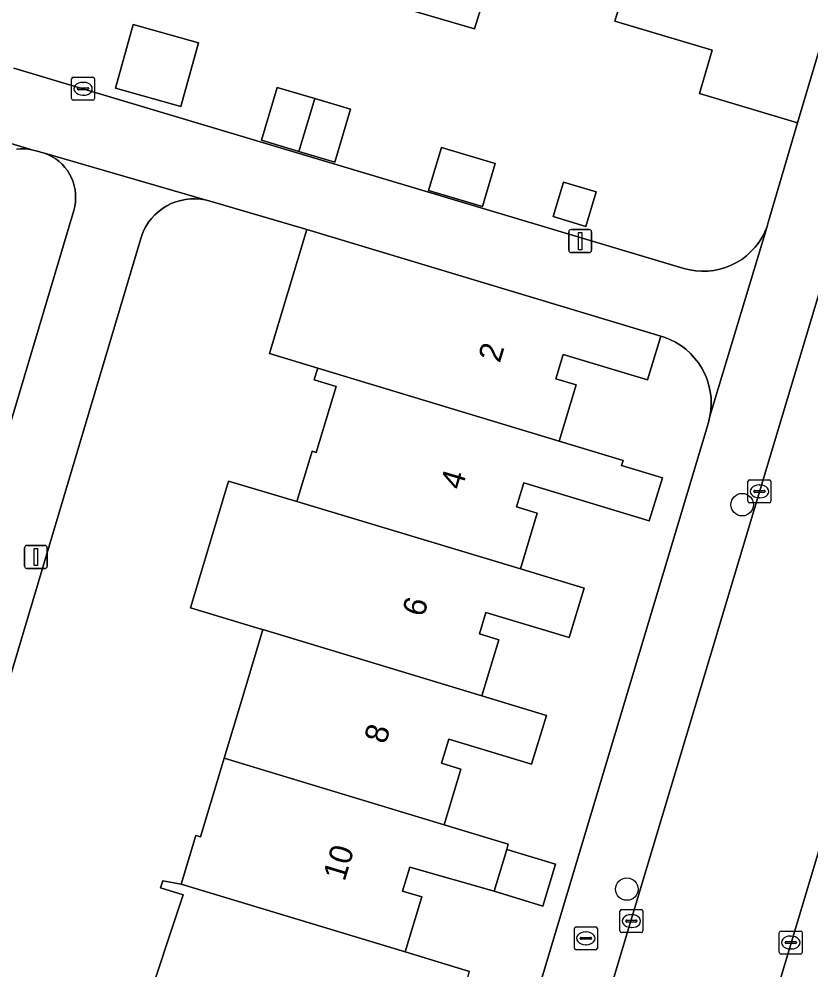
# Model space of a CAD drawing. Extents: x 162184 to 163154, y 385507 to 386516.
# Drawn here: x 162667.22 to 162701.67, y 386139.27 to 386180.64 of the extents above; entities that cross this region are included whole.
import ezdxf

# ---------------------------------------------------------------- set-up
doc = ezdxf.new("R2010")
doc.units = 0
for name, color, linetype in [('IMGEO_Boom', 7, 'Continuous'), ('IMGEO_Brandkraan', 7, 'Continuous'), ('IMGEO_Erf', 7, 'Continuous'), ('IMGEO_Groenvoorziening', 7, 'Continuous'), ('IMGEO_Kolk', 7, 'Continuous'), ('IMGEO_Lichtmast', 7, 'Continuous'), ('IMGEO_Pand', 7, 'Continuous'), ('IMGEO_Pand_nummerreeks', 7, 'Continuous'), ('IMGEO_Rijbaan_lokaal_open', 7, 'Continuous'), ('IMGEO_Voetpad_open', 7, 'Continuous')]:
    doc.layers.add(name, color=color, linetype=linetype)

msp = doc.modelspace()

# ---------------------------------------------------------------- linework, layer by layer
at = {"layer": 'IMGEO_Boom'}
for centre in [(162698.674, 386159.513), (162693.661, 386142.787)]:
    msp.add_circle(centre, 0.489, dxfattribs=at)
at = {"layer": 'IMGEO_Brandkraan'}
for p, q in [((162691.375, 386140.218), (162691.375, 386141.07)), ((162691.45, 386141.144), (162692.302, 386141.144)), ((162692.376, 386141.07), (162692.376, 386140.218)), ((162691.634, 386140.638), (162691.634, 386140.65)), ((162691.677, 386140.687), (162692.075, 386140.687)), ((162691.863, 386140.924), (162691.888, 386140.924)), ((162692.118, 386140.65), (162692.118, 386140.638)), ((162692.072, 386140.601), (162691.674, 386140.601)), ((162691.886, 386140.364), (162691.861, 386140.364)), ((162692.302, 386140.144), (162691.45, 386140.144))]:
    msp.add_line(p, q, dxfattribs=at)
for points in [[(162691.375, 386140.218), (162691.375, 386141.07)], [(162691.45, 386141.144), (162692.302, 386141.144)], [(162692.376, 386141.07), (162692.376, 386140.218)], [(162692.302, 386140.144), (162691.45, 386140.144)]]:
    msp.add_lwpolyline(points, dxfattribs=at)
for centre, radius, start, end in [((162691.452, 386141.068), 0.0765, 91.552, 178.448), ((162691.452, 386141.068), 0.0765, 91.552, 178.448), ((162692.3, 386141.068), 0.0765, 1.552, 88.448), ((162692.3, 386141.068), 0.0765, 1.552, 88.448), ((162691.674, 386140.647), 0.0403, 85.8775, 175.7526), ((162691.671, 386140.637), 0.0366, 178.938, 274.7102), ((162692.075, 386140.644), 0.043, 264.8664, 352.4533), ((162692.079, 386140.649), 0.0386, 1.7309, 96.639), ((162691.452, 386140.22), 0.0765, 181.552, 268.448), ((162691.452, 386140.22), 0.0765, 181.552, 268.448), ((162692.3, 386140.22), 0.0765, 271.552, 358.448), ((162692.3, 386140.22), 0.0765, 271.552, 358.448)]:
    msp.add_arc(centre, radius, start, end, dxfattribs=at)
for centre, major_axis, ratio, start_param, end_param in [((162691.862, 386140.644), (-0.387, 0.002), 0.722429, 4.712389, 7.853982), ((162691.887, 386140.644), (-0.39, 0.002), 0.717154, 1.570796, 4.712389)]:
    msp.add_ellipse(centre, major_axis=major_axis, ratio=ratio, start_param=start_param, end_param=end_param, dxfattribs=at)
at = {"layer": 'IMGEO_Erf'}
for points in [[(162687.686, 386182.336), (162687.034, 386180.211), (162681.466, 386181.862)], [(162666.99, 386178.501), (162696.144, 386169.794), (162696.399, 386169.73), (162696.658, 386169.689), (162696.92, 386169.671), (162697.183, 386169.677), (162697.444, 386169.706), (162697.701, 386169.758), (162697.953, 386169.833), (162698.197, 386169.931), (162698.431, 386170.049), (162698.654, 386170.188), (162698.864, 386170.347), (162699.058, 386170.524), (162699.236, 386170.717), (162699.396, 386170.925), (162699.537, 386171.147), (162699.657, 386171.381), (162699.756, 386171.624), (162699.811, 386171.795), (162701.088, 386176.13), (162696.812, 386177.398), (162697.373, 386179.289), (162693.133, 386180.547), (162693.464, 386181.665)], [(162672.648, 386137.382), (162674.361, 386142.543), (162673.38, 386142.839), (162673.471, 386143.139), (162674.27, 386142.997), (162674.91, 386145.116), (162675.113, 386145.055), (162676.018, 386148.053), (162676.147, 386148.481), (162676.849, 386150.83), (162677.083, 386151.605), (162677.829, 386154.075), (162677.646, 386154.13), (162674.678, 386155.026), (162676.339, 386160.538), (162679.31, 386159.652), (162679.97, 386161.838), (162680.144, 386161.785), (162681.011, 386164.658), (162680.056, 386164.946), (162680.142, 386165.23), (162680.211, 386165.459), (162678.11, 386166.096), (162679.739, 386171.493), (162675.532, 386172.716), (162675.323, 386172.77), (162675.11, 386172.804), (162674.895, 386172.82), (162674.679, 386172.816), (162674.464, 386172.793), (162674.252, 386172.751), (162674.045, 386172.691), (162673.844, 386172.612), (162673.651, 386172.515), (162673.468, 386172.401), (162673.295, 386172.272), (162673.134, 386172.128), (162672.987, 386171.969), (162672.855, 386171.799), (162672.739, 386171.617), (162672.639, 386171.426), (162672.557, 386171.226), (162672.514, 386171.096), (162664.259, 386143.414)], [(162682.002, 386112.374), (162697.211, 386163.095), (162697.274, 386163.359), (162697.313, 386163.627), (162697.329, 386163.897), (162697.32, 386164.168), (162697.286, 386164.437), (162697.229, 386164.702), (162697.149, 386164.961), (162697.045, 386165.212), (162696.92, 386165.452), (162696.774, 386165.68), (162696.608, 386165.894), (162696.423, 386166.093), (162696.222, 386166.274), (162696.005, 386166.437), (162695.774, 386166.579), (162695.532, 386166.701), (162695.279, 386166.8), (162695.132, 386166.846), (162694.556, 386164.939), (162690.882, 386166.049), (162690.564, 386164.995), (162691.448, 386164.729), (162690.709, 386162.279), (162693.498, 386161.437), (162693.433, 386161.221), (162695.203, 386160.686), (162694.635, 386158.808), (162692.865, 386159.342), (162689.171, 386160.457), (162688.856, 386159.412), (162689.762, 386159.138), (162689.033, 386156.722), (162691.807, 386155.884), (162691.156, 386153.728), (162687.527, 386154.823), (162687.245, 386153.889), (162688.087, 386153.635), (162687.35, 386151.194), (162690.162, 386150.346), (162689.514, 386148.228), (162685.909, 386149.316), (162685.592, 386148.265), (162686.442, 386148.008), (162685.712, 386145.589), (162688.503, 386144.747), (162688.433, 386144.514), (162690.56, 386143.872), (162690.01, 386142.049), (162687.883, 386142.691), (162684.213, 386143.742), (162683.898, 386142.699), (162684.738, 386142.445), (162684.015, 386140.05), (162686.809, 386139.206)]]:
    msp.add_lwpolyline(points, dxfattribs=at)
for points in [[(162674.253, 386176.841), (162671.416, 386177.634), (162672.191, 386180.407), (162675.028, 386179.613)], [(162680.081, 386177.186), (162681.643, 386176.723), (162680.96, 386174.42), (162679.398, 386174.883), (162677.763, 386175.368), (162678.446, 386177.671)], [(162685.036, 386173.183), (162685.591, 386175.054), (162687.933, 386174.358), (162687.377, 386172.488)], [(162690.454, 386172.046), (162690.898, 386173.542), (162692.322, 386173.12), (162691.878, 386171.623)]]:
    msp.add_lwpolyline(points, close=True, dxfattribs=at)
at = {"layer": 'IMGEO_Groenvoorziening'}
msp.add_lwpolyline([(162661.394, 386144.815), (162669.599, 386172.319), (162669.643, 386172.494), (162669.671, 386172.673), (162669.683, 386172.854), (162669.679, 386173.035), (162669.658, 386173.214), (162669.622, 386173.391), (162669.57, 386173.565), (162669.503, 386173.733), (162669.421, 386173.894), (162669.324, 386174.047), (162669.215, 386174.191), (162669.093, 386174.325), (162668.96, 386174.447), (162668.816, 386174.557), (162668.663, 386174.654), (162668.502, 386174.736), (162668.335, 386174.804), (162668.162, 386174.857), (162668.132, 386174.864), (162667.782, 386174.948), (162667.618, 386174.98), (162667.452, 386174.997), (162667.285, 386174.999), (162667.118, 386174.986)], dxfattribs=at)
at = {"layer": 'IMGEO_Kolk'}
for p, q in [((162669.507, 386177.183), (162669.507, 386178.035)), ((162669.582, 386178.109), (162670.434, 386178.109)), ((162669.995, 386177.889), (162670.02, 386177.889)), ((162670.508, 386178.035), (162670.508, 386177.183)), ((162669.766, 386177.603), (162669.766, 386177.615)), ((162670.204, 386177.566), (162669.806, 386177.566)), ((162669.809, 386177.652), (162670.207, 386177.652)), ((162670.25, 386177.615), (162670.25, 386177.603)), ((162670.434, 386177.109), (162669.582, 386177.109)), ((162670.018, 386177.329), (162669.993, 386177.329)), ((162698.925, 386159.664), (162698.925, 386160.516)), ((162699, 386160.59), (162699.852, 386160.59)), ((162699.926, 386160.516), (162699.926, 386159.664)), ((162699.184, 386160.084), (162699.184, 386160.096)), ((162699.227, 386160.133), (162699.625, 386160.133)), ((162699.413, 386160.37), (162699.438, 386160.37)), ((162699.668, 386160.096), (162699.668, 386160.084)), ((162699.622, 386160.047), (162699.224, 386160.047)), ((162699.436, 386159.81), (162699.411, 386159.81)), ((162699.852, 386159.59), (162699, 386159.59)), ((162693.43, 386141.894), (162694.282, 386141.894)), ((162693.355, 386140.968), (162693.355, 386141.82)), ((162693.843, 386141.674), (162693.868, 386141.674)), ((162694.356, 386141.82), (162694.356, 386140.968)), ((162693.614, 386141.388), (162693.614, 386141.4)), ((162694.052, 386141.351), (162693.654, 386141.351)), ((162693.657, 386141.437), (162694.055, 386141.437)), ((162693.866, 386141.114), (162693.841, 386141.114)), ((162694.098, 386141.4), (162694.098, 386141.388)), ((162694.282, 386140.894), (162693.43, 386140.894)), ((162700.29, 386140.035), (162700.29, 386140.887)), ((162700.365, 386140.961), (162701.217, 386140.961)), ((162700.778, 386140.741), (162700.803, 386140.741)), ((162701.291, 386140.887), (162701.291, 386140.035)), ((162700.549, 386140.455), (162700.549, 386140.467)), ((162700.987, 386140.418), (162700.589, 386140.418)), ((162700.592, 386140.504), (162700.99, 386140.504)), ((162701.033, 386140.467), (162701.033, 386140.455)), ((162701.217, 386139.961), (162700.365, 386139.961)), ((162700.801, 386140.181), (162700.776, 386140.181))]:
    msp.add_line(p, q, dxfattribs=at)
for points in [[(162669.507, 386177.183), (162669.507, 386178.035)], [(162669.582, 386178.109), (162670.434, 386178.109)], [(162670.508, 386178.035), (162670.508, 386177.183)], [(162670.434, 386177.109), (162669.582, 386177.109)], [(162698.925, 386159.664), (162698.925, 386160.516)], [(162699, 386160.59), (162699.852, 386160.59)], [(162699.926, 386160.516), (162699.926, 386159.664)], [(162699.852, 386159.59), (162699, 386159.59)], [(162693.43, 386141.894), (162694.282, 386141.894)], [(162693.355, 386140.968), (162693.355, 386141.82)], [(162694.356, 386141.82), (162694.356, 386140.968)], [(162694.282, 386140.894), (162693.43, 386140.894)], [(162700.29, 386140.035), (162700.29, 386140.887)], [(162700.365, 386140.961), (162701.217, 386140.961)], [(162701.291, 386140.887), (162701.291, 386140.035)], [(162701.217, 386139.961), (162700.365, 386139.961)]]:
    msp.add_lwpolyline(points, dxfattribs=at)
for centre, radius, start, end in [((162669.584, 386178.033), 0.0765, 91.552, 178.448), ((162669.584, 386178.033), 0.0765, 91.552, 178.448), ((162670.432, 386178.033), 0.0765, 1.552, 88.448), ((162670.432, 386178.033), 0.0765, 1.552, 88.448), ((162669.806, 386177.612), 0.0403, 85.8775, 175.7526), ((162669.803, 386177.602), 0.0366, 178.938, 274.7102), ((162670.207, 386177.609), 0.043, 264.8664, 352.4533), ((162670.211, 386177.614), 0.0386, 1.7309, 96.639), ((162669.584, 386177.185), 0.0765, 181.552, 268.448), ((162669.584, 386177.185), 0.0765, 181.552, 268.448), ((162670.432, 386177.185), 0.0765, 271.552, 358.448), ((162670.432, 386177.185), 0.0765, 271.552, 358.448), ((162699.002, 386160.514), 0.0765, 91.552, 178.448), ((162699.002, 386160.514), 0.0765, 91.552, 178.448), ((162699.85, 386160.514), 0.0765, 1.552, 88.448), ((162699.85, 386160.514), 0.0765, 1.552, 88.448), ((162699.224, 386160.093), 0.0403, 85.8775, 175.7526), ((162699.221, 386160.083), 0.0366, 178.938, 274.7102), ((162699.625, 386160.09), 0.043, 264.8664, 352.4533), ((162699.629, 386160.095), 0.0386, 1.7309, 96.639), ((162699.002, 386159.666), 0.0765, 181.552, 268.448), ((162699.002, 386159.666), 0.0765, 181.552, 268.448), ((162699.85, 386159.666), 0.0765, 271.552, 358.448), ((162699.85, 386159.666), 0.0765, 271.552, 358.448), ((162693.432, 386141.818), 0.0765, 91.552, 178.448), ((162693.432, 386141.818), 0.0765, 91.552, 178.448), ((162694.28, 386141.818), 0.0765, 1.552, 88.448), ((162694.28, 386141.818), 0.0765, 1.552, 88.448), ((162693.654, 386141.397), 0.0403, 85.8775, 175.7526), ((162693.651, 386141.387), 0.0366, 178.938, 274.7102), ((162694.055, 386141.394), 0.043, 264.8664, 352.4533), ((162694.059, 386141.399), 0.0386, 1.7309, 96.639), ((162693.432, 386140.97), 0.0765, 181.552, 268.448), ((162693.432, 386140.97), 0.0765, 181.552, 268.448), ((162694.28, 386140.97), 0.0765, 271.552, 358.448), ((162694.28, 386140.97), 0.0765, 271.552, 358.448), ((162700.367, 386140.885), 0.0765, 91.552, 178.448), ((162700.367, 386140.885), 0.0765, 91.552, 178.448), ((162701.215, 386140.885), 0.0765, 1.552, 88.448), ((162701.215, 386140.885), 0.0765, 1.552, 88.448), ((162700.589, 386140.464), 0.0403, 85.8775, 175.7526), ((162700.586, 386140.454), 0.0366, 178.938, 274.7102), ((162700.99, 386140.461), 0.043, 264.8664, 352.4533), ((162700.994, 386140.466), 0.0386, 1.7309, 96.639), ((162700.367, 386140.037), 0.0765, 181.552, 268.448), ((162700.367, 386140.037), 0.0765, 181.552, 268.448), ((162701.215, 386140.037), 0.0765, 271.552, 358.448), ((162701.215, 386140.037), 0.0765, 271.552, 358.448)]:
    msp.add_arc(centre, radius, start, end, dxfattribs=at)
for centre, major_axis, ratio, start_param, end_param in [((162669.994, 386177.609), (-0.387, 0.002), 0.722429, 4.712389, 7.853982), ((162670.019, 386177.609), (-0.39, 0.002), 0.717154, 1.570796, 4.712389), ((162699.412, 386160.09), (-0.387, 0.002), 0.722429, 4.712389, 7.853982), ((162699.437, 386160.09), (-0.39, 0.002), 0.717154, 1.570796, 4.712389), ((162693.842, 386141.394), (-0.387, 0.002), 0.722429, 4.712389, 7.853982), ((162693.867, 386141.394), (-0.39, 0.002), 0.717154, 1.570796, 4.712389), ((162700.777, 386140.461), (-0.387, 0.002), 0.722429, 4.712389, 7.853982), ((162700.802, 386140.461), (-0.39, 0.002), 0.717154, 1.570796, 4.712389)]:
    msp.add_ellipse(centre, major_axis=major_axis, ratio=ratio, start_param=start_param, end_param=end_param, dxfattribs=at)
at = {"layer": 'IMGEO_Lichtmast'}
for p, q in [((162691.134, 386170.583), (162691.134, 386171.383)), ((162691.134, 386171.383), (162691.134, 386170.583)), ((162691.234, 386171.483), (162692.024, 386171.483)), ((162692.024, 386171.483), (162691.234, 386171.483)), ((162692.124, 386171.383), (162692.124, 386170.583)), ((162692.124, 386170.583), (162692.124, 386171.383)), ((162692.024, 386170.483), (162691.234, 386170.483)), ((162691.234, 386170.483), (162692.024, 386170.483)), ((162667.461, 386156.838), (162667.461, 386157.638)), ((162667.461, 386157.638), (162667.461, 386156.838)), ((162667.561, 386157.738), (162668.351, 386157.738)), ((162668.351, 386157.738), (162667.561, 386157.738)), ((162668.451, 386157.638), (162668.451, 386156.838)), ((162668.451, 386156.838), (162668.451, 386157.638)), ((162668.351, 386156.738), (162667.561, 386156.738)), ((162667.561, 386156.738), (162668.351, 386156.738))]:
    msp.add_line(p, q, dxfattribs=at)
for points in [[(162691.554, 386171.358), (162691.704, 386171.358), (162691.704, 386170.608), (162691.554, 386170.608), (162691.554, 386171.358)], [(162667.881, 386157.613), (162668.031, 386157.613), (162668.031, 386156.863), (162667.881, 386156.863), (162667.881, 386157.613)]]:
    msp.add_lwpolyline(points, dxfattribs=at)
for centre, start, end in [((162691.234, 386171.383), 90, 180), ((162691.234, 386171.383), 90, 180), ((162692.024, 386171.383), 0, 90), ((162692.024, 386171.383), 360, 90), ((162691.234, 386170.583), 180, 270), ((162691.234, 386170.583), 180, 270), ((162692.024, 386170.583), 270, 0), ((162692.024, 386170.583), 270, 0), ((162667.561, 386157.638), 90, 180), ((162667.561, 386157.638), 90, 180), ((162668.351, 386157.638), 0, 90), ((162668.351, 386157.638), 360, 90), ((162667.561, 386156.838), 180, 270), ((162667.561, 386156.838), 180, 270), ((162668.351, 386156.838), 270, 0), ((162668.351, 386156.838), 270, 0)]:
    msp.add_arc(centre, 0.1, start, end, dxfattribs=at)
at = {"layer": 'IMGEO_Pand'}
for points in [[(162685.957, 386197.294), (162685.141, 386194.547), (162682.375, 386184.93), (162682.092, 386183.975), (162681.466, 386181.862), (162687.034, 386180.211), (162687.686, 386182.336), (162690.669, 386192.933), (162688.232, 386193.656), (162687.972, 386192.78), (162687.03, 386193.059), (162688.098, 386196.659)], [(162704.256, 386186.807), (162701.319, 386187.678), (162701.887, 386189.591), (162699.355, 386190.342), (162699.111, 386189.523), (162698.103, 386189.822), (162699.149, 386193.349), (162697.111, 386193.953), (162696.305, 386191.235), (162693.464, 386181.665), (162693.133, 386180.547), (162697.373, 386179.289), (162696.812, 386177.398), (162701.088, 386176.13)], [(162674.253, 386176.841), (162675.028, 386179.613), (162672.191, 386180.407), (162671.416, 386177.634)], [(162680.081, 386177.186), (162678.446, 386177.671), (162677.763, 386175.368), (162679.398, 386174.883)], [(162680.081, 386177.186), (162679.398, 386174.883), (162680.96, 386174.42), (162681.643, 386176.723)], [(162685.036, 386173.183), (162687.377, 386172.488), (162687.933, 386174.358), (162685.591, 386175.054)], [(162690.454, 386172.046), (162691.878, 386171.623), (162692.322, 386173.12), (162690.898, 386173.542)], [(162695.132, 386166.846), (162679.739, 386171.493), (162678.11, 386166.096), (162680.211, 386165.459), (162690.709, 386162.279), (162691.448, 386164.729), (162690.564, 386164.995), (162690.882, 386166.049), (162694.556, 386164.939)], [(162690.709, 386162.279), (162680.211, 386165.459), (162680.142, 386165.23), (162680.056, 386164.946), (162681.011, 386164.658), (162680.144, 386161.785), (162679.97, 386161.838), (162679.31, 386159.652), (162689.033, 386156.722), (162689.762, 386159.138), (162688.856, 386159.412), (162689.171, 386160.457), (162692.865, 386159.342), (162694.635, 386158.808), (162695.203, 386160.686), (162693.433, 386161.221), (162693.498, 386161.437)], [(162691.807, 386155.884), (162689.033, 386156.722), (162679.31, 386159.652), (162676.339, 386160.538), (162674.678, 386155.026), (162677.646, 386154.13), (162677.829, 386154.075), (162687.35, 386151.194), (162688.087, 386153.635), (162687.245, 386153.889), (162687.527, 386154.823), (162691.156, 386153.728)], [(162687.35, 386151.194), (162677.829, 386154.075), (162677.083, 386151.605), (162676.849, 386150.83), (162676.147, 386148.481), (162685.712, 386145.589), (162686.442, 386148.008), (162685.592, 386148.265), (162685.909, 386149.316), (162689.514, 386148.228), (162690.162, 386150.346)], [(162685.712, 386145.589), (162676.147, 386148.481), (162676.018, 386148.053), (162675.113, 386145.055), (162674.91, 386145.116), (162674.27, 386142.997), (162684.015, 386140.05), (162684.738, 386142.445), (162683.898, 386142.699), (162684.213, 386143.742), (162687.883, 386142.691), (162688.433, 386144.514), (162688.503, 386144.747)], [(162688.433, 386144.514), (162687.883, 386142.691), (162690.01, 386142.049), (162690.56, 386143.872)], [(162684.015, 386140.05), (162674.27, 386142.997), (162673.471, 386143.139), (162673.38, 386142.839), (162674.361, 386142.543), (162672.648, 386137.382), (162682.338, 386134.462), (162683.081, 386136.924), (162682.254, 386137.173), (162682.562, 386138.191), (162686.173, 386137.101), (162686.224, 386137.27), (162686.809, 386139.206)]]:
    msp.add_lwpolyline(points, close=True, dxfattribs=at)
at = {"layer": 'IMGEO_Rijbaan_lokaal_open'}
msp.add_lwpolyline([(162729.19, 386259.752), (162728.39, 386256.734), (162726.379, 386250), (162719.4, 386226.716), (162710.296, 386196.346), (162684.842, 386111.426), (162691.517, 386109.426), (162697.472, 386129.304), (162699.069, 386134.636), (162733.627, 386250)], dxfattribs=at)
at = {"layer": 'IMGEO_Voetpad_open'}
msp.add_lwpolyline([(162721.387, 386198.465), (162721.434, 386198.607), (162723.685, 386206.143), (162723.746, 386206.383), (162728.84, 386223.351), (162728.866, 386223.475), (162730.951, 386230.401), (162730.989, 386230.496), (162735.341, 386245.037), (162736.826, 386250), (162733.627, 386250), (162699.069, 386134.636), (162699.516, 386134.501), (162701.942, 386133.579), (162703.362, 386138.221), (162703.404, 386138.39), (162703.662, 386139.272), (162703.7, 386139.388), (162705.601, 386145.815), (162705.654, 386146.025)], close=True, dxfattribs=at)
for points in [[(162707.388, 386197.091), (162706.911, 386195.922), (162704.932, 386188.998), (162704.89, 386188.895), (162704.256, 386186.807), (162701.088, 386176.13), (162699.811, 386171.795), (162699.756, 386171.624), (162697.274, 386163.359), (162697.211, 386163.095), (162682.002, 386112.374), (162681.973, 386107.91)], [(162684.842, 386111.426), (162710.296, 386196.346)], [(162661.428, 386176.867), (162667.782, 386174.948), (162668.132, 386174.864), (162668.162, 386174.857), (162668.335, 386174.804), (162675.323, 386172.77), (162675.532, 386172.716), (162679.739, 386171.493), (162695.132, 386166.846), (162695.279, 386166.8), (162695.532, 386166.701), (162695.774, 386166.579), (162696.005, 386166.437), (162696.222, 386166.274), (162696.423, 386166.093), (162696.608, 386165.894), (162696.774, 386165.68), (162696.92, 386165.452), (162697.045, 386165.212), (162697.149, 386164.961), (162697.229, 386164.702), (162697.286, 386164.437), (162697.32, 386164.168), (162697.329, 386163.897), (162697.313, 386163.627), (162697.274, 386163.359), (162699.756, 386171.624), (162699.657, 386171.381), (162699.537, 386171.147), (162699.396, 386170.925), (162699.236, 386170.717), (162699.058, 386170.524), (162698.864, 386170.347), (162698.654, 386170.188), (162698.431, 386170.049), (162698.197, 386169.931), (162697.953, 386169.833), (162697.701, 386169.758), (162697.444, 386169.706), (162697.183, 386169.677), (162696.92, 386169.671), (162696.658, 386169.689), (162696.399, 386169.73), (162696.144, 386169.794), (162666.99, 386178.501)], [(162667.118, 386174.986), (162667.285, 386174.999), (162667.452, 386174.997), (162667.618, 386174.98), (162667.782, 386174.948), (162661.428, 386176.867)], [(162664.259, 386143.414), (162672.514, 386171.096), (162672.557, 386171.226), (162672.639, 386171.426), (162672.739, 386171.617), (162672.855, 386171.799), (162672.987, 386171.969), (162673.134, 386172.128), (162673.295, 386172.272), (162673.468, 386172.401), (162673.651, 386172.515), (162673.844, 386172.612), (162674.045, 386172.691), (162674.252, 386172.751), (162674.464, 386172.793), (162674.679, 386172.816), (162674.895, 386172.82), (162675.11, 386172.804), (162675.323, 386172.77), (162668.335, 386174.804), (162668.502, 386174.736), (162668.663, 386174.654), (162668.816, 386174.557), (162668.96, 386174.447), (162669.093, 386174.325), (162669.215, 386174.191), (162669.324, 386174.047), (162669.421, 386173.894), (162669.503, 386173.733), (162669.57, 386173.565), (162669.622, 386173.391), (162669.658, 386173.214), (162669.679, 386173.035), (162669.683, 386172.854), (162669.671, 386172.673), (162669.643, 386172.494), (162669.599, 386172.319), (162661.394, 386144.815)]]:
    msp.add_lwpolyline(points, dxfattribs=at)

# ---------------------------------------------------------------- texts
at = {"layer": 'IMGEO_Pand_nummerreeks'}
for s, p in [('2', (162688.131, 386165.648)), ('4', (162686.476, 386160.119)), ('6', (162684.821, 386154.588)), ('8', (162683.168, 386149.062)), ('10', (162681.382, 386143.089))]:
    msp.add_text(s, height=1, rotation=73.3443, dxfattribs=at).set_placement(p)

doc.saveas('drawing.dxf')
